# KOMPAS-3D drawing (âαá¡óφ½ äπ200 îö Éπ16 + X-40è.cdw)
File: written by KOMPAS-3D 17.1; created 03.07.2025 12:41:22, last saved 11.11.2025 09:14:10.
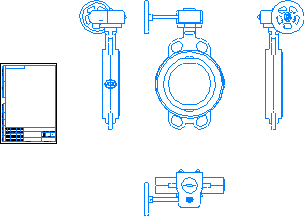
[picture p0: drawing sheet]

Sheet 1: A4, portrait

Title block, sheet 1: sheets: 1; sheet format: A4; stored path: \\adlc.lan\data\АДЛ_ПКД\3D-модели\ADL production\Дисковые поворотные затворы ГРАНВЭЛ\межфланцевый с китайским редуктором Ру16\KOMPAS 2D\Гранвэл Ду200 МФ Ру16 + X-40К.cdw

Views: Вид 1, Спереди, Проекционный вид 2, Проекционный вид 3, Проекционный вид 4
Referenced files in \\adlc.lan\data\АДЛ_ПКД\3D-модели\ADL production\Дисковые поворотные затворы ГРАНВЭЛ\межфланцевый с китайским редуктором Ру16\KOMPAS 3D\: Гранвэл Ду200 МФ Ру16 + X-40К.m3d
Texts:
  Andrey
  АДЛ
Dimensions and other numbers on the sheet: 1:1; 1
